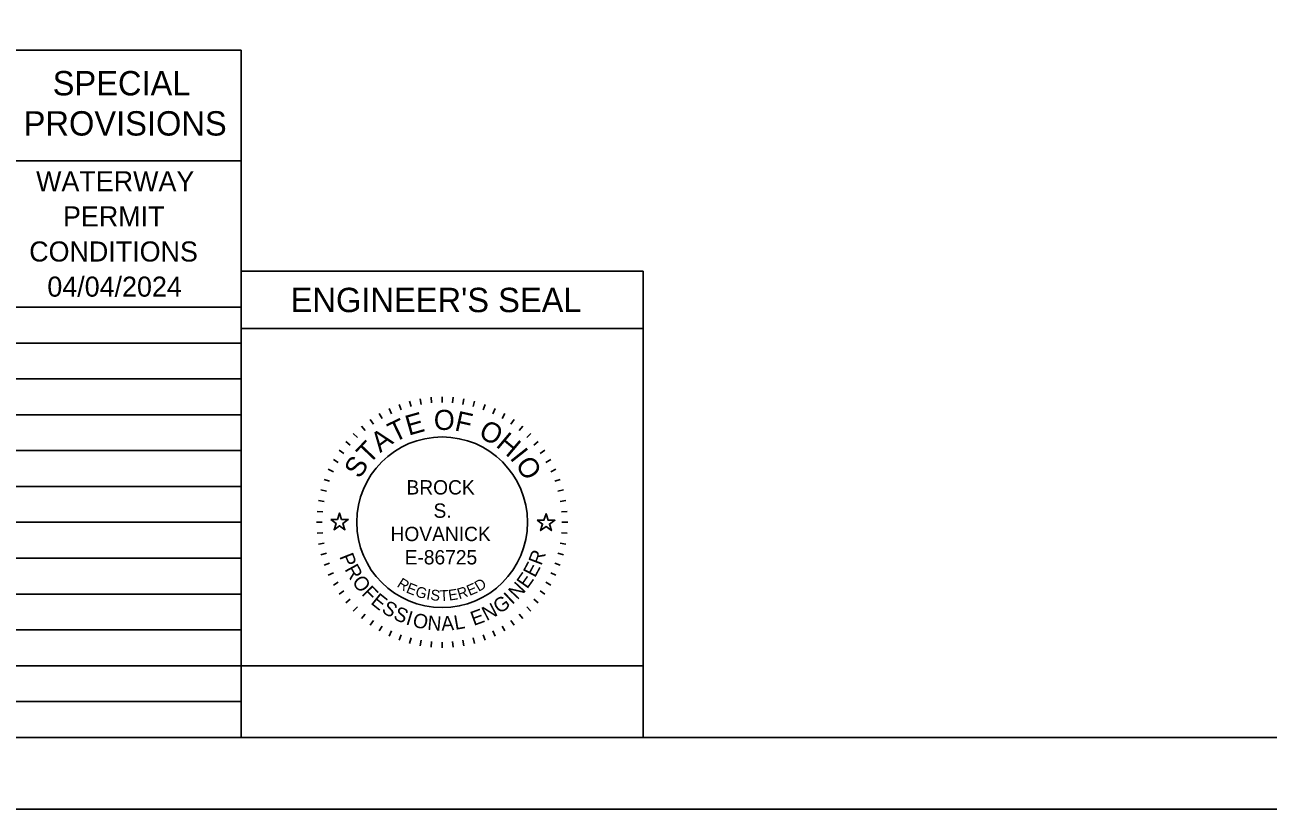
# Model space of a CAD drawing. Extents: x -7.5 to 53.5, y 0 to 22.
# Drawn here: x 23.19 to 31.86, y 0 to 5.47 of the extents above; entities that cross this region are included whole.
import ezdxf

# ---------------------------------------------------------------- set-up
doc = ezdxf.new("R2010")
doc.units = 0
for name, color, linetype in [('SH_Border', 7, 'Continuous'), ('SH_Cut_Line', 7, 'Continuous'), ('SH_Data', 7, 'Continuous'), ('SH_Text', 7, 'Continuous')]:
    doc.layers.add(name, color=color, linetype=linetype)

msp = doc.modelspace()

# ---------------------------------------------------------------- linework, layer by layer
at = {"layer": 'SH_Border'}
msp.add_lwpolyline([(1.5, 21.5), (33.5, 21.5), (33.5, 0.5), (1.5, 0.5)], close=True, dxfattribs=at)
at = {"layer": 'SH_Cut_Line'}
msp.add_lwpolyline([(0, 0), (34, 0), (34, 22), (0, 22)], close=True, dxfattribs=at)
at = {"layer": 'SH_Data'}
for p, q in [((11.25, 5.2917), (24.7, 5.2917)), ((24.7, 0.5), (24.7, 5.2917)), ((11.25, 4.5209), (24.7, 4.5209)), ((24.7, 0.5), (24.7, 3.75)), ((24.7, 3.75), (27.5, 3.75)), ((27.5, 3.75), (27.5, 0.5)), ((11.25, 3.5), (24.7, 3.5)), ((24.7, 3.35), (27.5, 3.35)), ((11.25, 3.25), (24.7, 3.25)), ((11.25, 3), (24.7, 3)), ((25.9481, 2.8617), (25.955, 2.8223)), ((26.0237, 2.8717), (26.0272, 2.8318)), ((26.1, 2.875), (26.1, 2.835)), ((26.1763, 2.8717), (26.1728, 2.8318)), ((26.2519, 2.8617), (26.245, 2.8223)), ((25.7302, 2.793), (25.7471, 2.7568)), ((25.8007, 2.8222), (25.8144, 2.7846)), ((25.8735, 2.8452), (25.8839, 2.8065)), ((26.3265, 2.8452), (26.3161, 2.8065)), ((26.3993, 2.8222), (26.3856, 2.7846)), ((26.4698, 2.793), (26.4529, 2.7568)), ((11.25, 2.75), (24.7, 2.75)), ((25.5981, 2.7168), (25.6211, 2.684)), ((25.6625, 2.7578), (25.6825, 2.7231)), ((26.5375, 2.7578), (26.5175, 2.7231)), ((26.6019, 2.7168), (26.5789, 2.684)), ((25.4813, 2.6187), (25.5096, 2.5904)), ((25.5376, 2.6703), (25.5633, 2.6396)), ((26.6624, 2.6703), (26.6367, 2.6396)), ((26.7187, 2.6187), (26.6904, 2.5904)), ((25.4297, 2.5624), (25.4604, 2.5367)), ((26.7703, 2.5624), (26.7396, 2.5367)), ((11.25, 2.5), (24.7, 2.5)), ((25.3422, 2.4375), (25.3769, 2.4175)), ((25.3832, 2.5019), (25.416, 2.4789)), ((26.8168, 2.5019), (26.784, 2.4789)), ((26.8578, 2.4375), (26.8231, 2.4175)), ((25.307, 2.3698), (25.3432, 2.3529)), ((26.893, 2.3698), (26.8568, 2.3529)), ((25.2778, 2.2993), (25.3154, 2.2856)), ((26.9222, 2.2993), (26.8846, 2.2856)), ((11.25, 2.25), (24.7, 2.25)), ((25.2548, 2.2265), (25.2935, 2.2161)), ((26.9452, 2.2265), (26.9065, 2.2161)), ((25.2383, 2.1519), (25.2777, 2.145)), ((26.9617, 2.1519), (26.9223, 2.145)), ((11.25, 2), (24.7, 2)), ((25.225, 2), (25.265, 2)), ((25.2283, 2.0763), (25.2682, 2.0728)), ((26.9717, 2.0763), (26.9318, 2.0728)), ((26.975, 2), (26.935, 2)), ((25.2283, 1.9237), (25.2682, 1.9272)), ((26.9717, 1.9237), (26.9318, 1.9272)), ((25.2383, 1.8481), (25.2777, 1.855)), ((26.9617, 1.8481), (26.9223, 1.855)), ((11.25, 1.75), (24.7, 1.75)), ((25.2548, 1.7735), (25.2935, 1.7839)), ((26.9452, 1.7735), (26.9065, 1.7839)), ((25.2778, 1.7007), (25.3154, 1.7144)), ((25.307, 1.6302), (25.3432, 1.6471)), ((26.893, 1.6302), (26.8568, 1.6471)), ((26.9222, 1.7007), (26.8846, 1.7144)), ((25.3422, 1.5625), (25.3769, 1.5825)), ((26.8578, 1.5625), (26.8231, 1.5825)), ((11.25, 1.5), (24.7, 1.5)), ((25.3832, 1.4981), (25.416, 1.5211)), ((26.8168, 1.4981), (26.784, 1.5211)), ((25.4297, 1.4376), (25.4604, 1.4633)), ((25.4813, 1.3813), (25.5096, 1.4096)), ((26.7187, 1.3813), (26.6904, 1.4096)), ((26.7703, 1.4376), (26.7396, 1.4633)), ((25.5376, 1.3297), (25.5633, 1.3604)), ((25.5981, 1.2832), (25.6211, 1.316)), ((26.6019, 1.2832), (26.5789, 1.316)), ((26.6624, 1.3297), (26.6367, 1.3604)), ((11.25, 1.25), (24.7, 1.25)), ((25.6625, 1.2422), (25.6825, 1.2769)), ((25.7302, 1.207), (25.7471, 1.2432)), ((25.8007, 1.1778), (25.8144, 1.2154)), ((26.3993, 1.1778), (26.3856, 1.2154)), ((26.4698, 1.207), (26.4529, 1.2432)), ((26.5375, 1.2422), (26.5175, 1.2769)), ((25.8735, 1.1548), (25.8839, 1.1935)), ((25.9481, 1.1383), (25.955, 1.1777)), ((26.0237, 1.1283), (26.0272, 1.1682)), ((26.1, 1.125), (26.1, 1.165)), ((26.1763, 1.1283), (26.1728, 1.1682)), ((26.2519, 1.1383), (26.245, 1.1777)), ((26.3265, 1.1548), (26.3161, 1.1935)), ((11.25, 1), (24.7, 1)), ((11.25, 0.75), (24.7, 0.75)), ((24.7, 0.5), (27.5, 0.5))]:
    msp.add_line(p, q, dxfattribs=at)
for points in [[(25.3236, 2.02), (25.3705, 2.02), (25.385, 2.0645), (25.3995, 2.02), (25.4464, 2.02), (25.4085, 1.9924), (25.423, 1.9478), (25.385, 1.9754), (25.347, 1.9478), (25.3615, 1.9924)], [(26.7627, 2.0146), (26.8096, 2.0146), (26.8241, 2.0591), (26.8386, 2.0146), (26.8855, 2.0146), (26.8476, 1.987), (26.8621, 1.9424), (26.8241, 1.97), (26.7861, 1.9424), (26.8006, 1.987)], [(24.7, 0.5), (24.7, 1), (27.5, 1), (27.5, 0.5)]]:
    msp.add_lwpolyline(points, close=True, dxfattribs=at)
msp.add_circle((26.1, 2), 0.595, dxfattribs=at)

# ---------------------------------------------------------------- texts
for s, height, p in [('WATERWAY', 0.14, (23.2709, 4.308)), ('PERMIT', 0.14, (23.4583, 4.063)), ('CONDITIONS', 0.14, (23.223, 3.818)), ('04/04/2024', 0.14, (23.3494, 3.573)), ("ENGINEER'S SEAL", 0.17, (25.0448, 3.465)), ('BROCK', 0.1, (25.8517, 2.1937)), ('S.', 0.1, (26.0401, 2.0312)), ('HOVANICK', 0.1, (25.7404, 1.8687)), ('E-86725', 0.1, (25.8388, 1.7062))]:
    msp.add_text(s, height=height, dxfattribs=at).set_placement(p)
for s, height, rotation, p in [('O', 0.14, 359.78119, (26.042, 2.6442)), ('F', 0.14, 347.43619, (26.1811, 2.6417)), ('T', 0.14, 25.71674, (25.7661, 2.554)), ('E', 0.14, 15.75706, (25.8669, 2.6034)), ('O', 0.14, 332.25863, (26.3463, 2.5981)), ('A', 0.14, 36.47472, (25.6685, 2.4819)), ('H', 0.14, 319.91363, (26.4684, 2.5316)), ('T', 0.14, 46.4344, (25.5917, 2.4)), ('I', 0.14, 308.36695, (26.5674, 2.4471)), ('S', 0.14, 57.19238, (25.526, 2.2981)), ('O', 0.14, 303.14906, (26.6061, 2.4028)), ('P', 0.1, 291.49398, (25.3823, 1.7619)), ('R', 0.1, 69.23216, (26.7913, 1.6936)), ('R', 0.1, 298.73106, (25.4181, 1.6733)), ('E', 0.1, 54.75801, (26.6928, 1.5306)), ('E', 0.1, 61.99508, (26.7472, 1.609)), ('O', 0.1, 306.46664, (25.4682, 1.5845)), ('F', 0.1, 314.7068, (25.5343, 1.4983)), ('R', 0.075, 327.82385, (25.7801, 1.554)), ('E', 0.075, 337.77772, (25.8439, 1.5128)), ('E', 0.075, 23.30524, (26.2909, 1.4856)), ('D', 0.075, 31.46601, (26.355, 1.5136)), ('N', 0.1, 47.02243, (26.6242, 1.455)), ('E', 0.1, 321.43929, (25.597, 1.4354)), ('G', 0.075, 344.27273, (25.9082, 1.4848)), ('I', 0.075, 350.64643, (25.9868, 1.4634)), ('S', 0.075, 353.78581, (26.0155, 1.4581)), ('T', 0.075, 3.00609, (26.0852, 1.4505)), ('E', 0.075, 8.98261, (26.1492, 1.453)), ('R', 0.075, 17.68363, (26.2187, 1.4627)), ('G', 0.1, 35.04687, (26.4997, 1.3581)), ('I', 0.1, 43.28703, (26.5876, 1.4221)), ('S', 0.1, 328.67637, (25.6722, 1.3766)), ('S', 0.1, 335.91345, (25.7541, 1.3276)), ('E', 0.1, 20.07421, (26.3203, 1.2767)), ('N', 0.1, 27.31129, (26.4097, 1.3102)), ('I', 0.1, 343.15053, (25.8416, 1.2894)), ('O', 0.1, 346.88592, (25.8884, 1.2741)), ('N', 0.1, 355.12608, (25.9946, 1.2512)), ('A', 0.1, 2.86166, (26.0964, 1.2439)), ('L', 0.1, 10.09874, (26.1917, 1.2494))]:
    msp.add_text(s, height=height, rotation=rotation, dxfattribs=at).set_placement(p)
at = {"layer": 'SH_Text'}
for s, p in [('SPECIAL', (23.3864, 4.9763)), ('PROVISIONS', (23.1843, 4.6963))]:
    msp.add_text(s, height=0.17, dxfattribs=at).set_placement(p)

doc.saveas('drawing.dxf')
